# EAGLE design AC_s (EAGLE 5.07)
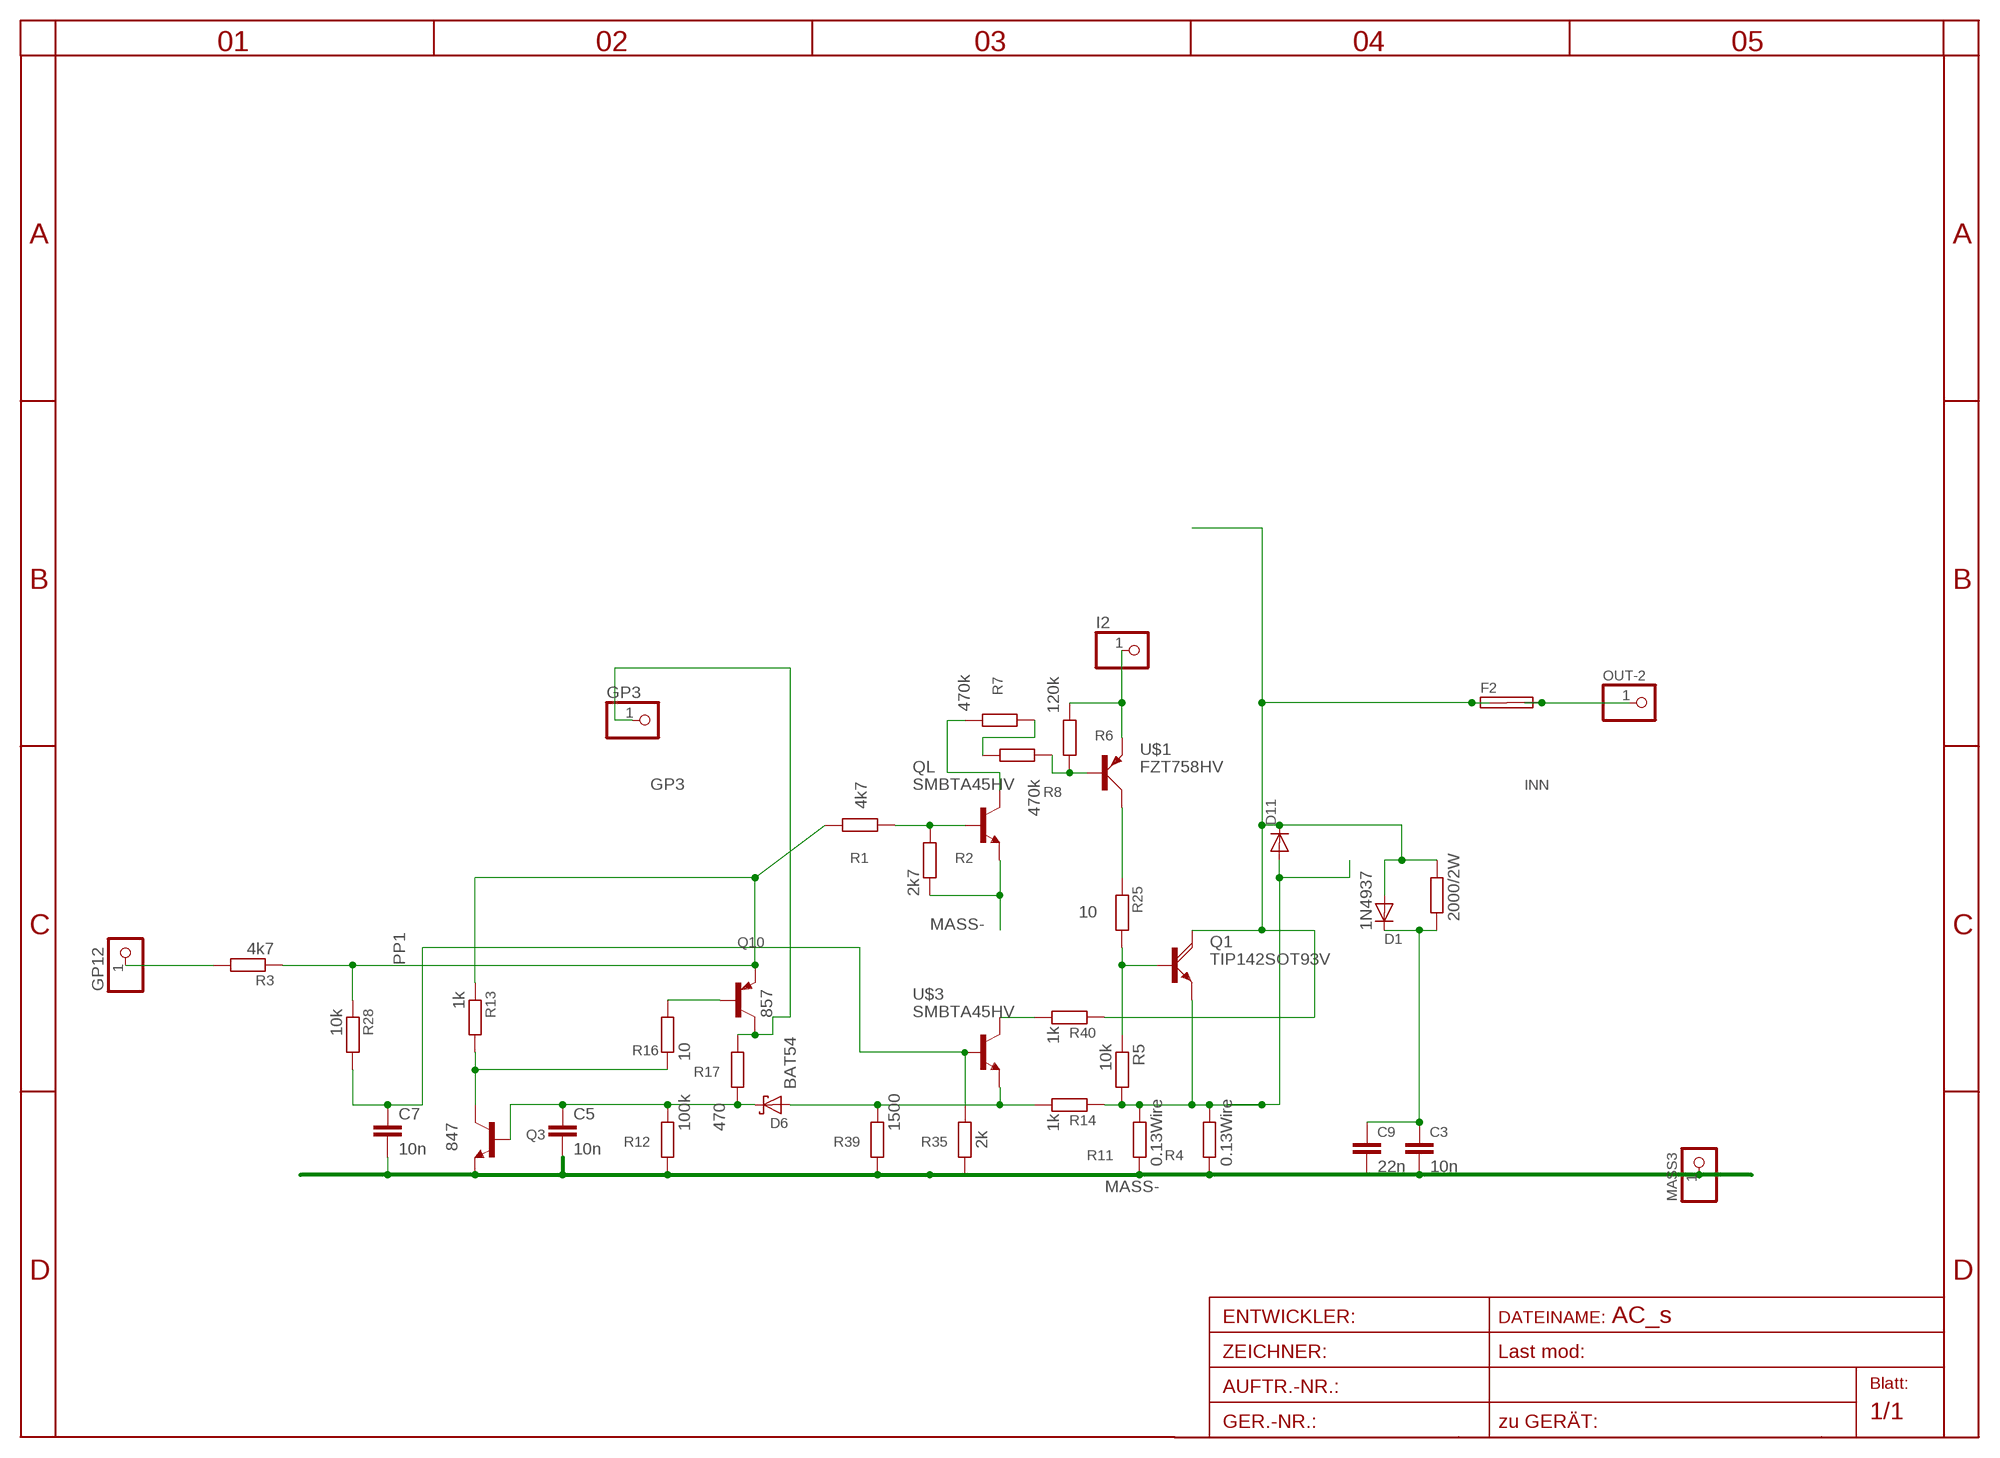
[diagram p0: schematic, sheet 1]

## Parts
C3  10n  C-EU025_050-050X075  [C025_050-050X075]
C5  10n  C-EUC0805  [C0805]
C7  10n  C-EUC0805  [C0805]
C9  22n  C-EU150-054X183  [C150-054X183]
D1  1N4937  1N4004DO41-10  [DO41-10]
D6  BAT54  [SOT23]
D11  DIODE-SMC  [SMC]
F2  SHK20L7MM5  [7MM5]
GP3  PINHD-1X11X0.4  [1X01]
GP12  PINHD-1X11X0.4  [1X01]
I2  PINHD-1X11X0.4  [1X01]
MASS3  PINHD-1X13MM2  [1X3MM2]
OUT-2  PINHD-1X13MM2  [1X3MM2]
Q1  TIP142SOT93V  [SOT93V]
Q3  847  BC846ALT1SMD  [SOT23]
Q10  857  BC857ALT1SMD  [SOT23-BEC]
QL  SMBTA45HV  [SOT23HV]
R1  4k7  R-EU_R0805  [R0805]
R2  2k7  R-EU_R0805  [R0805]
R3  4k7  R-EU_R0805  [R0805]
R4  0.13Wire  R-EU_0204/5  [0204/5]
R5  10k  R-EU_0207/15  [0207/15]
R6  120k  R-EU_R1206  [R1206]
R7  470k  R-EU_R1206  [R1206]
R8  470k  R-EU_R1206  [R1206]
R11  0.13Wire  R-EU_0204/5  [0204/5]
R12  100k  R-EU_R0805  [R0805]
R13  1k  R-EU_R0805  [R0805]
R14  1k  R-EU_R0805  [R0805]
R16  10  R-EU_R0805  [R0805]
R17  470  R-EU_R0805  [R0805]
R25  10  R-EU_0207/25  [0207/25]
R27  2000/2W  R-EU_0207/10  [0207/10]
R28  10k  R-EU_R0805  [R0805]
R35  2k  R-EU_R0805  [R0805]
R39  1500  R-EU_R0805  [R0805]
R40  1k  R-EU_R1206  [R1206]
U$1  FZT758HV  [SOT223HV]
U$3  SMBTA45HV  [SOT23HV]

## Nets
BQL: QL.1(B) R1.2 R2.2
CT1: R25.1 U$1.2(C1)
D1: D1.A D11.C F2.1A F2.1B Q1.C R27.2 R40.2
DK1: C5.1 D6.3(C) Q3.1(B) R12.1 R17.2
FUSE: GP3.1 Q10.C R17.1
GP3: Q3.3(C) R13.2 R16.1
INN: F2.2A F2.2B OUT-2.1
MASS-: C3.3 C5.2 C7.2 C9.2 MASS3.1 Q3.2(E) QL.2(E) R2.1 R4.1 R11.1 R12.2 R35.2 R39.2
N$1: R7.1 R8.2
N$2: C3.1 C9.1 D1.C R27.1
N$4: Q1.B R5.1 R25.2
N$6: R6.1 R8.1 U$1.1(B)
N$7: I2.1 R6.2 U$1.3(E)
N$9: QL.3(C) R7.2
N$12: GP12.1 R3.2
N$14: R40.1 U$3.3(C)
N$16: Q10.B R16.2
N$40: C7.1 R28.2 R35.1 U$3.1(B)
PP1: Q10.E R1.1 R3.1 R13.1 R28.1
SRC1: D11.A Q1.E R4.2 R5.2 R11.2 R14.2
T1E: D6.1(A) R14.1 R39.1 U$3.2(E)
Unconnected: U$1.4(C)

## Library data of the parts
C3 C9 = rcl-2:C-EU: CAPACITOR, European symbol
C5 C7 = rcl:C-EU: CAPACITOR, European symbol
D1 = diode:1N4004: DIODE
D6 = diode:BAT54: Schottky Diodes
D11 = diode:DIODE-: DIODE
F2 = fuse:SHK20L: FUSE HOLDER 5 x 20 mm, SH contact, SHH1 Schukat, E1073 Buerklin
GP3 GP12 I2 MASS3 OUT-2 = pinhead:PINHD-1X1: PIN HEADER
Q1 = transistor-power:TIP142: NPN DARLINGTON TRANSISTOR
Q3 = transistor-npn:BC846*: NPN Transistor
Q10 = transistor-pnp:BC857*: PNP Transistror
QL U$3 = transistor-npn:SMBTA45
R1-R8 R11-R14 R16 R17 R25 R27 R28 R35 R39 R40 = rcl-2:R-EU_: RESISTOR, European symbol
U$1 = transistor-power:FZT758

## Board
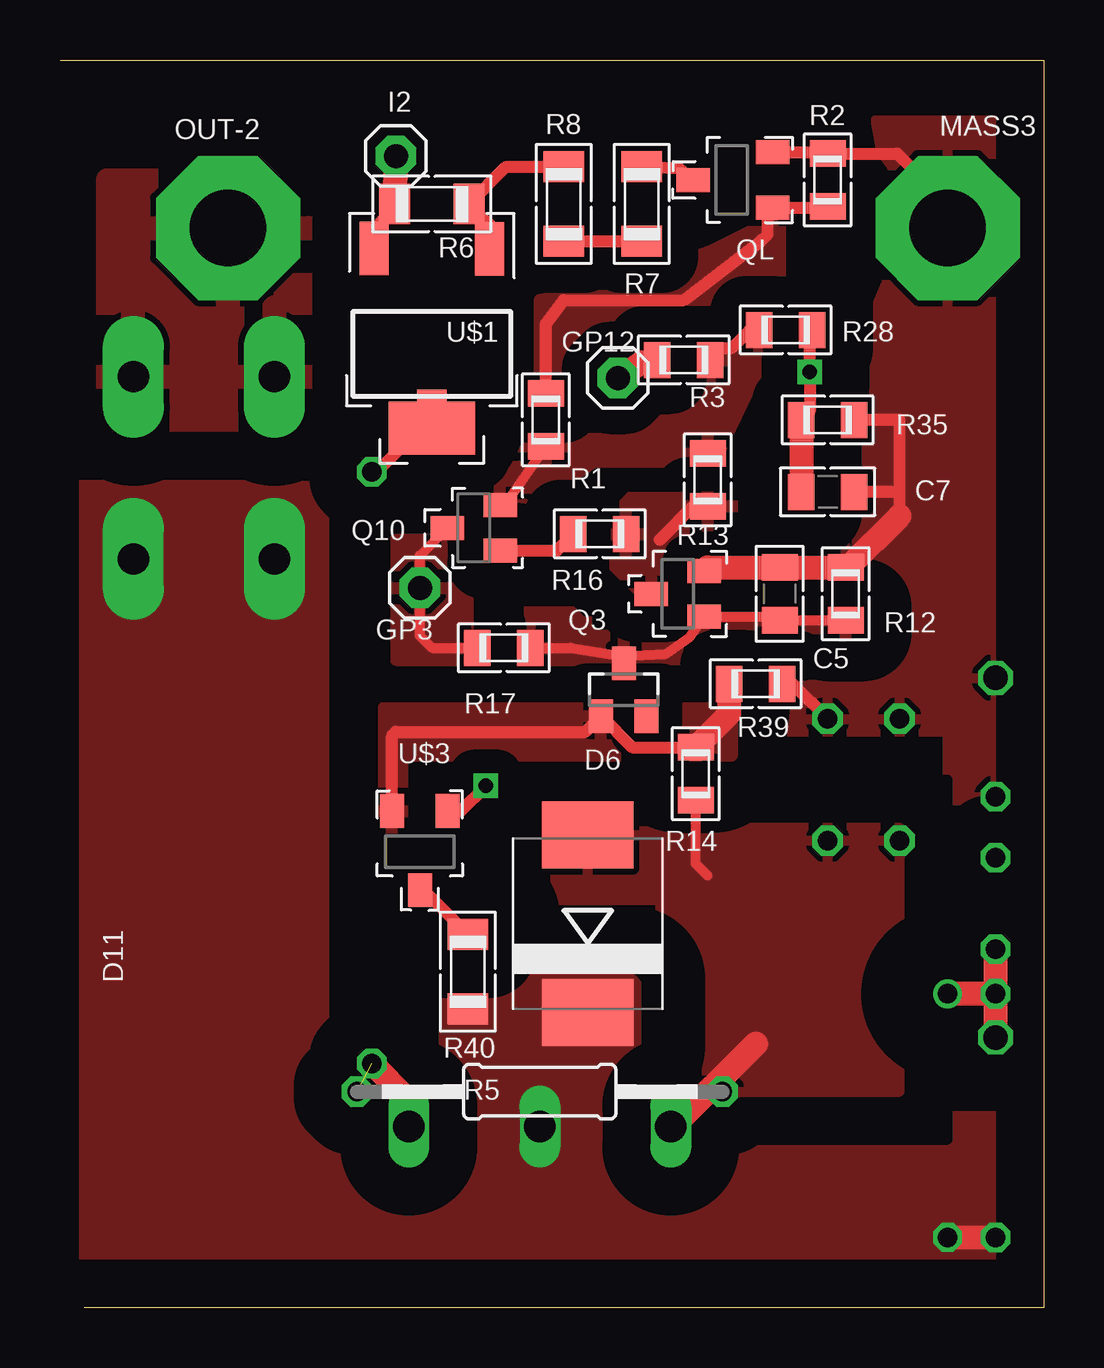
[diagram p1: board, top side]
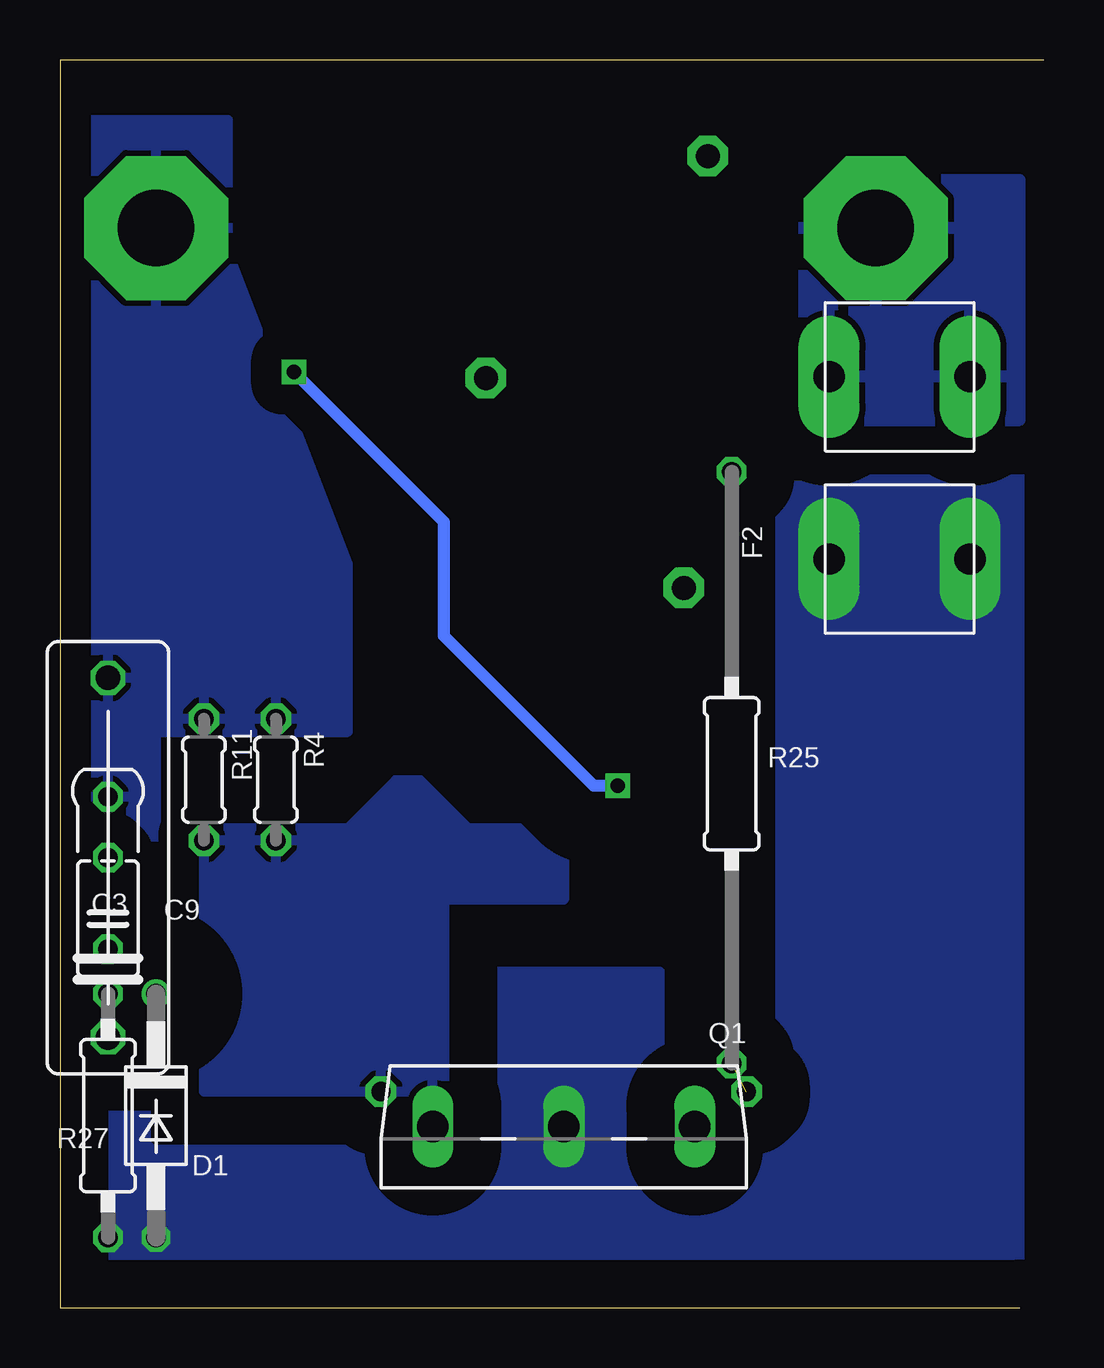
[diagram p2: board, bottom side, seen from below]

Size 41 x 52 mm. Coordinates in mm from the lower left corner, seen from the top.
Outline: 0,52 41,52 41,0 1,0
Copper layers (1*16): Top 0.035mm / dielectric 1.5mm / Bottom 0.035mm
Design rules "default *": minimum track width 12mil, minimum drill 24mil, track to track 8mil, track to pad 8mil, pad to pad 8mil, via to via 8mil, smd to smd 8mil, copper to edge 40mil, drill to drill 8mil, minimum pad ring 8mil, minimum via ring 8mil, stop-mask expansion 4mil, vias tented up to drill 0mil, thermal gap 10mil

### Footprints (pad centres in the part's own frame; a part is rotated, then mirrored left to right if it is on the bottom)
C025_050-050X075 = drill 0.813 octagon: 1 -3.81,0; 2 0,0; 3 2.54,0
C0805 = smd 1.1 x 1.5: 1 -1.1,0; 2 1.1,0
C150-054X183 = drill 1.016 octagon: 1 -7.493,0; 2 7.493,0
DO41-10 = drill 0.8 octagon: A 5.08,0 | drill 0.8 round: C -5.08,0
SOT23 = smd 1 x 1.4: 1 -0.95,-1.1; 2 0.95,-1.1; 3 0,1.1
SMC = smd 2.8 x 3.8: A 3.7,0; C -3.7,0
7MM5 = drill 1.3 pad 2.54 long: 1A -3.8,2.94; 1B -3.8,-2.94; 2A 3.8,2.94; 2B 3.8,-2.94
1X01 = drill 1 pad 1.676 octagon: 1 0,0
1X3MM2 = drill 3.2 pad 6 octagon: 1 0,0
SOT93V = drill 1.3 pad 1.676 long: B -5.461,-2.54; C 0,-2.54; E 5.461,-2.54
SOT23-BEC = smd 1 x 1.4: B -0.95,-1.1; C 0,1.1; E 0.95,-1.1
SOT23HV = smd 1 x 1.4: 1 -1.15,-1.7; 2 1.15,-1.7; 3 0,1.6
R0805 = smd 1.1 x 1.5: 1 -1.1,0; 2 1.1,0
0204/5 = drill 0.8 pad 1.27 octagon: 1 -2.54,0; 2 2.54,0
0207/15 = drill 0.8 pad 1.27 octagon: 1 -7.62,0; 2 7.62,0
R1206 = smd 1.3 x 1.7: 1 -1.55,0; 2 1.55,0
0207/25 = drill 0.813 octagon: 1 -12.58,0; 2 12.08,0
0207/10 = drill 0.813 octagon: 1 -5.08,0; 2 5.08,0
SOT223HV = smd 1.219 x 2.235: 1 -2.411,-4.369; 2 0,2.616; 3 2.411,-4.399 | smd 3.6 x 2.2: 4 0,3.099

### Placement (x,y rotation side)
C3  39,18.75 90 bottom
C5  30,29.75 90 top
C7  32,34 0 top
C9  39,18.75 90 bottom
D1  37,8 270 bottom
D6  23.5,25.75 0 top
D11  22,16 90 top
F2  6,35 90 bottom
GP3  15,30 0 top
GP12  23.25,38.75 0 top
I2  14,48 0 top
MASS3  37,45 0 top
OUT-2  7,45 180 top
Q1  20,5 180 bottom
Q3  25.75,29.75 90 top
Q10  17.25,32.5 90 top
QL  28,47 90 top
R1  20.25,37 90 top
R2  32,47 270 top
R3  26,39.5 180 top
R4  32,22 270 bottom
R5  20,9 0 top
R6  15.5,46 180 top
R7  24.25,46 90 top
R8  21,46 270 top
R11  35,22 270 bottom
R12  32.75,29.75 90 top
R13  27,34.5 270 top
R14  26.5,22.25 270 top
R16  22.5,32.25 180 top
R17  18.5,27.5 0 top
R25  13,22.25 270 bottom
R27  39,8 270 bottom
R28  30.25,40.75 0 top
R35  32,37 0 top
R39  29,26 0 top
R40  17,14 270 top
U$1  15.5,39.75 180 top
U$3  15,19 180 top

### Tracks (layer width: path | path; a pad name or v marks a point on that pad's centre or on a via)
BQL
  Top 0.5: R1.2 20.25,41 21,42 26,42 29.25,44.5 29.5,44.75 29.5,45.9 QL.1 31.95,45.85 R2.2
  pour Top (isolate 1.5): 29,45 30,46 30,42 25,42 22,40 22,39 21,38 20,38 20,42 27,44
CT1
  Top 0.5: R25.1 13.2,34.83 U$1.2
D1
  Top 1: D1.A R27.2
  pour Top (isolate 2, rank 2, no thermals): 1,0 1,35 11,35 11,11 16,11 16,14 24,14 24,8 40,8 41,7 41,0
  pour Bottom (isolate 2, rank 2, no thermals): 1,0 1,35 11,35 11,11 16,11 16,14 24,14 24,8 40,8 41,7 41,0
DK1
  Top 0.406: 23.4,27.15 D6.3 | 23.4,27.15 25.25,27.25 26.25,27.95 Q3.1 29.6,28.8 C5.1 R12.1 | R17.2 21.3,27.5 23.4,27.15
  pour Top (isolate 1.5, rank 4): 33,30 33,28 28,28 26,26 20,26 19,27 19,29 26,29 27,30
FUSE
  Top 0.406: R17.1 15.5,27.5 15,28 15,31.35 Q10.C
  pour Top (isolate 1.5): 17,32 14,32 14,27 17,27
GP3
  Top 0.5: R13.2 26.4,33.4 25,32
  pour Top (isolate 1, rank 3): 23,33 24,34 28,34 28,32 27,31 26,31 25,30 24,30 23,31
INN
  pour Top: 10,37 2,37 2,47 10,47
  pour Bottom: 10,37 1,37 1,47 10,47
MASS-
  Top 0.5: QL.2 31.95,48.15 R2.1 34.9,48.1 37,46 MASS3.1 | R39.2 30.54,26 R4.1 | Q3.2 27,30.85 | R35.2 35,37 35,34 | 35,34 C7.2 | R12.2 32.85,30.85 | 35,33 35,34
  Top 1: R12.2 C5.2 27,30.85 | 32.85,30.85 35,33
  pour Top (isolate 2, rank 2): 34,49.5 40,49.5 40,17 37,17 37,24 29,24 29,28 32,29 32,37 35,44
  pour Bottom (isolate 1.27, rank 2): 34,49.5 40,49.5 40,17 37,17 37,24 29,24 29,31 34,44
N$1
  Top 0.5: R8.2 R7.1
N$2
  Top 1: D1.C R27.1 C9.1 C3.1
N$4  (1 unrouted)
  Top 1: Q1.B 14.54,8.63 R25.2
N$6
  Top 0.5: U$1.1 17.91,45.14 R6.1 18.6,47.55 R8.1
N$7
  Top 0.406: I2.1 13.69,46.69
  Top 0.5: U$1.3 13.09,44.89 R6.2
  Top 1.016: R6.2 I2.1
N$9
  Top 0.5: QL.3 25.8,47.5 R7.2
N$12
  Top 1: GP12.1 24.25,39.4 R3.2
N$14
  Top 0.5: U$3.3 15.15,17.4 R40.1
N$16
  Top 0.5: Q10.B 20.7,31.55 R16.2
N$40  (via drill 0.6)
  Top 0.5: U$3.1 16.7,20.7 v17.75,21.75 | R35.1 31.25,37.35 v31.25,39 31.25,40.65 R28.2
  Top 1: R35.1 C7.1
  Bottom 0.5: v17.75,21.75 18.75,21.75 25,28 25,32.75 v31.25,39
PP1
  Top 0.406: Q10.E 18.55,33.45 R1.1
  Top 0.5: R28.1 28.75,40.75 28,40 27.6,40 R3.1
  pour Top (isolate 1.5, rank 2): 29,41 30,41 27.25,35.25 22.25,35.25 19,33 18,33 18,34 19,35 20,37 27,38 27,40
SRC1
  Top 0.406: R14.2 26.5,18.5 27,18
  Top 1.016: Q1.E 25.54,7.54 29,11
  pour Top (isolate 3): 25,9 35,9 35,20 29,20 27,22 26,22 24,20 20,20 20,17 25,17
  pour Bottom (isolate 3): 25,9 35,9 35,20 29,20 27,22 26,22 24,20 20,20 20,17 25,17
T1E
  Top 0.5: U$3.2 13.85,23.85 14,24 21.9,24 D6.1 23.85,23.35 R14.1
  Top 1: R39.1 27.9,24.75 R14.1
  pour Top (isolate 1): 14.25,20 13.5,20 13.5,25 27,25 28,26 28,23 14.25,23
